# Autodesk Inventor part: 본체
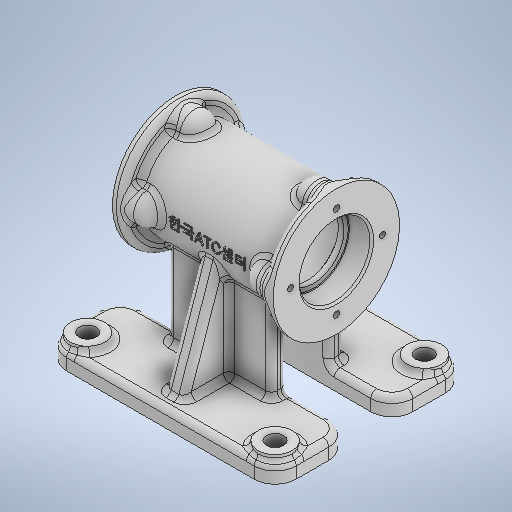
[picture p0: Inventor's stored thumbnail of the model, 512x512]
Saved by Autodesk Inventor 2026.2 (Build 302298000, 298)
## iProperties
Created: 2026-06
Part Number: 본체
Material: 알루미늄 6061
Document SubType Name: Modeling
Designer: sec7
Density: 2.7 g/cm^3
Appearance: 알루미늄 - 평지
Mass: 612.993 g
Surface Area: 669.716 cm^2
Volume: 227.034 cm^3
Author: sec7
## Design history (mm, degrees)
sketch "스케치1"
  geometry: L1 (-42, 25)-(42, 25); L2 (42, 25)-(42, 0); L3 (42, 0)-(-42, 0); L4 (-42, 0)-(-42, 25); L5 (-60, -61)-(60, -61); L6 (60, -61)-(60, -70); L7 (60, -70)-(-60, -70); L8 (-60, -70)-(-60, -61); 3 further points
  constraints: 16 end point, 4 parallel, 2 horizontal, 2 midpoint, 2 perpendicular, 1 coincident, 1 vertical alignment
  dimensions: "d0" = 84 distance of L1.start L1.end; "d1" = 50 diameter of L1 L3; "d2" = 70 vertical distance of L6.end L2.end; "d3" = 120 distance of L6.end L7.end; "d4" = 9 distance of L5.end L6.end
revolve "회전1" stored, may be unused: angle "d5" = 90 deg
sketch "스케치2"
  geometry: L1 (-27, -20.118)-(27, -20.118); L2 (27, -20.118)-(27, -50); L3 (27, -50)-(-27, -50); L4 (-27, -50)-(-27, -20.118); L5 (-60, -61)-(60, -61) reference; L6 (60, -70)-(-60, -70) reference; 2 further points
  constraints: 8 end point, 2 parallel, 1 horizontal, 1 midpoint, 1 perpendicular, 1 vertical alignment
  dimensions: "d6" = 54 distance of L1.start L1.end; "d8" = 20 distance between parallel lines of L6 L3
node "작업 평면3"
node "작업 평면2"
sketch "스케치4"
  geometry: L1 (11, -70)-(50, -70); L2 (50, -70)-(50, -61); L3 (50, -61)-(11, -61); L4 (11, -61)-(11, -70); L5 (11, -61)-(19, -61); L6 (19, -61)-(19, -12); L7 (19, -12)-(11, -12); L8 (11, -12)-(11, -61); 2 further points
  constraints: 16 end point, 4 parallel, 2 horizontal, 2 perpendicular
  dimensions: "d16" = 39 distance of L1.start L1.end; "d17" = 8 distance between parallel lines of L8 L6; "d18" = 9 distance of L1.end L2.end; "d19" = 11 distance from line of L4 point (0, 0); "d22" = 70 distance from line of L1 point (0, 0)
extrude "돌출3" join sketch "스케치4" stored distance "d23" = 120; taper "d24" = 0 deg
extrude "돌출4" join sketch "스케치4" stored distance "d25" = 54; taper "d26" = 0 deg
sketch "스케치6"
  geometry: L1 (-18, 14)-(-50, 14); L2 (-50, 14)-(-50, -14); L3 (-50, -14)-(-18, -14); L4 (-18, -14)-(-18, 14); L5 (-70, -50)-(-70, -11) reference; 1 further point
  constraints: 8 end point, 2 parallel, 1 horizontal, 1 perpendicular
  dimensions: "d30" = 20 distance between parallel lines of L5 L2
extrude "돌출6" join sketch "스케치6" stored distance "d31" = 10; taper "d32" = 0 deg
node "작업 평면5"
sketch "스케치7"
  geometry: L1 (43, -61)-(23.841, -5.358); L2 (23.841, -5.358)-(14.884, -5.358); L3 (-11, -50)-(11, -50) reference; L4 (14.884, -5.358)-(14.884, -61); L5 (14.884, -61)-(43, -61); L6 (50, -61)-(50, -70) reference; L7 (11, -61)-(50, -61) reference; 1 further point
  constraints: 8 end point, 2 perpendicular, 1 collinear, 1 parallel
  dimensions: "d33" = 19 deg angle of L4 L1; "d34" = 7 distance from line of L6 L1.start
extrude "돌출7" join sketch "스케치7" stored distance "d35" = 10; taper "d36" = 0 deg
sketch "스케치8"
  geometry: L1 (-42, 33)-(-37, 33); L2 (-37, 33)-(-37, 0); L3 (-37, 0)-(-42, 0); L4 (-42, 25)-(-42, -25) reference; L5 (42, 0)-(37, 0); L6 (37, 0)-(37, 33); L7 (37, 33)-(42, 33); L8 (-42, 33)-(-42, -25); L9 (42, 33)-(42, -25); L10 (42, -25)-(-42, -25) reference; 5 further points
  constraints: 16 end point, 3 parallel, 2 horizontal, 2 perpendicular, 1 collinear, 1 point on line
  dimensions: "d38" = 66 diameter of L1 L3; "d39" = 5 distance of L1.start L1.end; "d40" = 5 distance of L6.end L7.end; "d41" = 33 distance of L7.end L5.start; "d43" = 84 distance between parallel lines of L9 L4
revolve "회전3" sketch "스케치8" stored, may be unused: angle "d44" = 90 deg
sketch "스케치9" dims "d45" = 48
  geometry: C1 r 8 at (0, 24); 4 further points
  constraints: 1 centre point, 1 coincident, 3 other
  dimensions: "d46" = 16 diameter of C1
extrude "돌출8" join sketch "스케치9" distance "d47" = 13; taper "d48" = 0 deg
fillet "모깎기1" dims "d49" = 8
sketch "스케치10"
  geometry: L1 (-42, -33)-(-42, 33) reference; L2 (-42, 18.5)-(-30.3, 18.5); L3 (-30, 18.2)-(-30, 0); L4 (-30, 0)-(-42, 0); L5 (-42, 0)-(-42, 18.5); L6 (-30, 16)-(-27, 16); L7 (-27, 16)-(-27, 0); L8 (-27, 0)-(-30, 0); L9 (-30, 0)-(-30, 16); L10 (-27, 20)-(27, 20); L11 (27, 20)-(27, 0); L12 (27, 0)-(-27, 0); L13 (-27, 0)-(-27, 20); L14 (27, 16)-(30, 16); L15 (30, 16)-(30, 0); L16 (30, 0)-(27, 0); L17 (27, 0)-(27, 16); L18 (30, 0)-(42, 0); L19 (42, 0)-(42, 18.5); L20 (42, 18.5)-(30.3, 18.5); L21 (30, 18.2)-(30, 0); L22 (42, -33)-(42, 33) reference; A1 r 0.3 centre (-30.3, 18.2) between (-30, 18.2) and (-30.3, 18.5); A2 r 0.3 centre (30.3, 18.2) between (30.3, 18.5) and (30, 18.2); 10 further points
  constraints: 40 end point, 13 point on line, 10 parallel, 5 horizontal, 5 perpendicular, 4 point on circle, 4 tangent, 2 centre point, 1 collinear, 1 equal radius, 1 midpoint, 1 vertical alignment
  dimensions: "d53" = 37 diameter of L2 L4; "d54" = 32 diameter of L6 L12; "d55" = 40 diameter of L10 L12; "d56" = 12 distance of L2.start point (-30, 18.5); "d57" = 12 distance of L19.end point (30, 18.5); "d58" = 54 distance of L10.start L10.end; "d59" = 0.3 radius of A1
revolve "회전4" sketch "스케치10" stored, may be unused: angle "d60" = 90 deg
chamfer "모따기1" distance "d61" = 1; stored, may be unused: second distance "d62" = 2, angle "d63" = 45 deg
sketch "스케치11" dims "d64" = 48
  geometry: 3 further points
  constraints: 2 vertical alignment, 1 coincident, 2 other
hole "구멍1" sketch "스케치11" at (0, 24) diameter "d65" = 3.242; stored, may be unused: countersink angle "d69" = 90 deg, drill point angle "d71" = 120 deg; dims "d66" = 8, "d67" = 28, "d68" = 2, "d70" = 10
fillet "모깎기2" dims "d75" = 11
sketch "스케치12"
  geometry: L1 (-76, 69)-(22, 69) reference; L2 (33, 58)-(33, 41) reference; L3 (22, 30)-(0, 30) reference; L4 (0, 30)-(-54, 30) reference; L5 (-54, 38)-(-54, 30) reference; L6 (-32, 38)-(-54, 38) reference; L7 (-32, 62)-(-32, 38) reference; L8 (-22, 62)-(-32, 62) reference; L9 (-22, 38)-(-22, 62) reference; L10 (0, 38)-(-22, 38) reference; L11 (0, 30)-(0, 38) reference; L12 (-87, 41)-(-87, 58) reference; L13 (-54, 30)-(-76, 30) reference; L14 (33, -3)-(33, -20) reference; L15 (22, -31)-(-76, -31) reference; L16 (-87, -20)-(-87, -3) reference; L17 (-76, 8)-(-54, 8) reference; L18 (-54, 8)-(0, 8) reference; L19 (0, 0)-(0, 8) reference; L20 (-22, 0)-(0, 0) reference; L21 (-22, -24)-(-22, 0) reference; L22 (-32, -24)-(-22, -24) reference; L23 (-32, 0)-(-32, -24) reference; L24 (-54, 0)-(-32, 0) reference; L25 (-54, 8)-(-54, 0) reference; L26 (0, 8)-(22, 8) reference; C1 r 9 at (-76, 58); C2 r 9 at (22, 58); C3 r 9 at (22, -20); C4 r 9 at (-76, -20); A1 r 11 centre (-76, 58) between (-76, 69) and (-87, 58) reference; A2 r 11 centre (22, 58) between (33, 58) and (22, 69) reference; A3 r 11 centre (22, 41) between (22, 30) and (33, 41) reference; A4 r 11 centre (-76, 41) between (-87, 41) and (-76, 30) reference; A5 r 11 centre (22, -3) between (33, -3) and (22, 8) reference; A6 r 11 centre (22, -20) between (22, -31) and (33, -20) reference; A7 r 11 centre (-76, -20) between (-87, -20) and (-76, -31) reference; A8 r 11 centre (-76, -3) between (-76, 8) and (-87, -3) reference; 1 further point
  constraints: 4 centre point, 4 coincident
  dimensions: "d76" = 18 diameter of C1; "d77" = 18 diameter of C2; "d78" = 18 diameter of C3; "d79" = 18 diameter of C4
extrude "돌출9" join sketch "스케치12" distance "d80" = 3; taper "d81" = 0 deg
sketch "스케치13"
  geometry: L1 (-54, 58)-(-54, 80.967) reference; L2 (-54, 80.967)-(-44, 80.967) reference; L3 (-44, 80.967)-(-44, 58) reference; L4 (-44, 58)-(-22, 58) reference; L5 (-22, 58)-(-22, 50) reference; L6 (-22, 50)-(-76, 50) reference; L7 (-76, 50)-(-76, 58) reference; L8 (-76, 58)-(-54, 58) reference; L9 (-44, 20)-(-44, -2.967) reference; L10 (-44, -2.967)-(-54, -2.967) reference; L11 (-54, -2.967)-(-54, 20) reference; L12 (-54, 20)-(-76, 20) reference; L13 (-76, 20)-(-76, 28) reference; L14 (-76, 28)-(-22, 28) reference; L15 (-22, 28)-(-22, 20) reference; L16 (-22, 20)-(-44, 20) reference; C1 r 9 at (0, 78) reference; C2 r 9 at (0, 0) reference; C3 r 9 at (-98, 78) reference; C4 r 9 at (-98, 0) reference; C5 r 4.5 at (-98, 78); C6 r 4.5 at (0, 78); C7 r 4.5 at (0, 0); C8 r 4.5 at (-98, 0); 1 further point
  constraints: 4 centre point, 4 coincident
  dimensions: "d82" = 9 diameter of C5; "d83" = 9 diameter of C6; "d84" = 9 diameter of C7; "d85" = 9 diameter of C8
extrude "돌출10" cut sketch "스케치13" extent not by distance; stored distance "d86" = 0; taper "d87" = 0 deg
fillet "모깎기3" dims "d88" = 3
fillet "모깎기4" dims "d89" = 3
fillet "모깎기5" dims "d90" = 3
fillet "모깎기6" dims "d91" = 3
fillet "모깎기7" dims "d92" = 3
fillet "모깎기8" dims "d93" = 3
fillet "모깎기9" dims "d94" = 3
fillet "모깎기12" dims "d97" = 3
fillet "모깎기13" dims "d98" = 3
fillet "모깎기14" dims "d99" = 3
node "작업 평면6"
sketch "스케치14"
  geometry: L1 (0, 0)-(98, 0) reference; 2 further points
  constraints: 1 coincident, 1 other
  dimensions: "d101" = 70 distance from line of L1 point (49, 70)
feature "엠보싱2" sketch "스케치14" dims "d104" = 0.5, "d105" = 0
fillet "모깎기15" dims "d106" = 3
fillet "모깎기16" dims "d107" = 3
fillet "모깎기17" dims "d108" = 3
fillet "모깎기10" dims "d95" = 3
fillet "모깎기11" dims "d96" = 3
feature "ߘ耀ߚ耀ߜ耀ߞ耀ߠ耀ߢ耀ߤ耀ߦ耀" dims "d0" = 84, "d1" = 50, "d2" = 70, "d3" = 120, "d4" = 9, "d5" = 90 deg, "d6" = 54, "d8" = 20, "d16" = 39, "d17" = 8, "d18" = 9, "d19" = 11, "d22" = 70, "d23" = 120, "d24" = 0, "d25" = 54, "d26" = 0, "d30" = 20, "d31" = 10, "d32" = 0, "d33" = 19 deg, "d34" = 7, "d35" = 10, "d36" = 0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
node "솔리드1"
mirror "미러1"
mirror "미러2"
pattern_circular "원형 패턴1" dims "d51" = 360 deg
mirror "미러3"
pattern_circular "원형 패턴2" dims angle "d73" = 360 deg
mirror "미러4"
node "절단 모서리 투영1"
node "절단 모서리 투영2"
feature "A9D066F2-1C7D-4E18-AEED-F7BC21143FA4" dims "d65" = 3.242, "d66" = 8, "d67" = 28, "d68" = 2, "d69" = 90 deg, "d70" = 10, "d71" = 120 deg
